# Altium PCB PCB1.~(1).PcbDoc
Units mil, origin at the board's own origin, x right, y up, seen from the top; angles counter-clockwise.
Board outline 500 x 700 mil, 2 copper layers (Top Layer, Bottom Layer); 0 components, 0 nets, 4 pads, 0 vias.
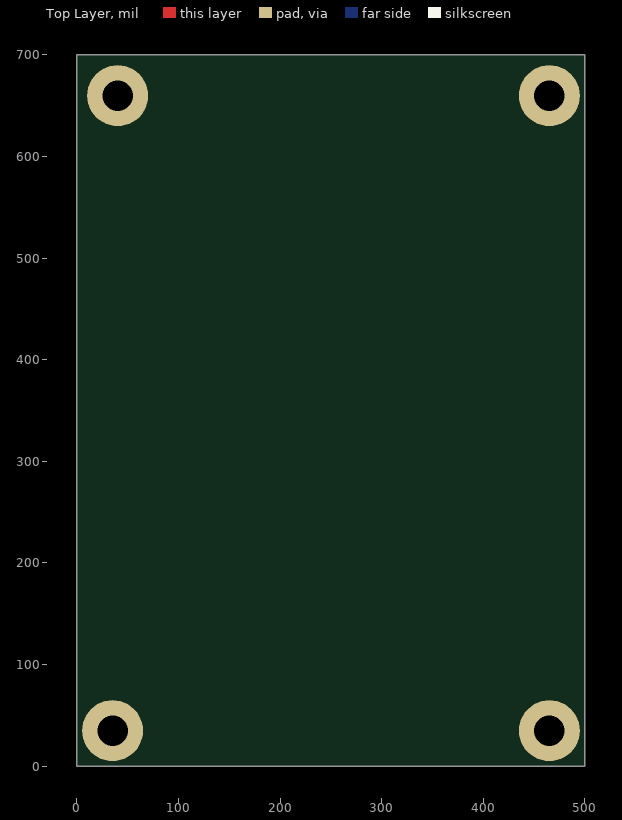
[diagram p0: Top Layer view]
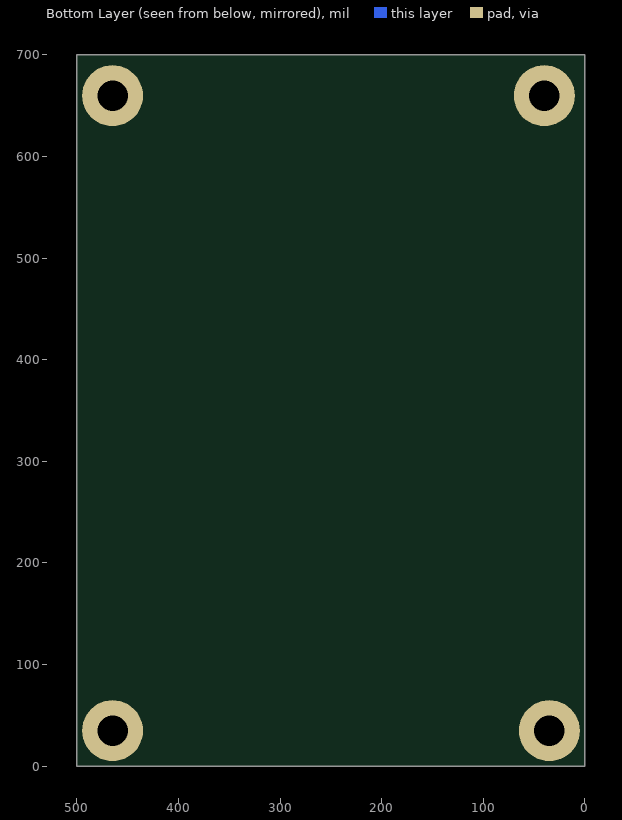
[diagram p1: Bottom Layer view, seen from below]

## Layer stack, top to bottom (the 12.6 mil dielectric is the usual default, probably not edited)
Top Solder: solder mask 0.4, Solder Resist, Dk 3.5
Top Layer: signal copper 1.4
Dielectric 1: dielectric 12.6, FR-4, Dk 4.8
Bottom Layer: signal copper 1.4
Bottom Solder: solder mask 0.4, Solder Resist, Dk 3.5

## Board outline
0,0 500,0 500,700 0,700

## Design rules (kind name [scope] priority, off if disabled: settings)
Clearance [All] p1: gap=10 ignorepadtopadclearanceinfootprint=FALSE
PolygonConnect [All] p1: connectstyle=Relief reliefconductorwidth=10 reliefentries=4 polygonreliefangle="90 Angle" airgapwidth=10
RoutingVias [All] p1: holewidth=28 width=50 viastyle="Through Hole" minholewidth=28 minwidth=50 maxholewidth=28 maxwidth=50
SolderMaskExpansion [All] p1: expansion=4 istentingtop=FALSE
Width [All] p1: maxlimit=10 minlimit=10 preferedwidth=10
30 further rules are at their usual default settings.

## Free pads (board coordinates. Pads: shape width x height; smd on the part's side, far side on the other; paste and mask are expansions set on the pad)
  round 60 hole 30: 1(40,660) 2(465,660) 3(465,35) 4(35,35)

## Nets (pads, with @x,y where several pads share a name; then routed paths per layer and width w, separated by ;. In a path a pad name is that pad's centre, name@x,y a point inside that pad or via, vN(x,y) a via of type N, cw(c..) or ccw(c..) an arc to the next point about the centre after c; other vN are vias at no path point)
